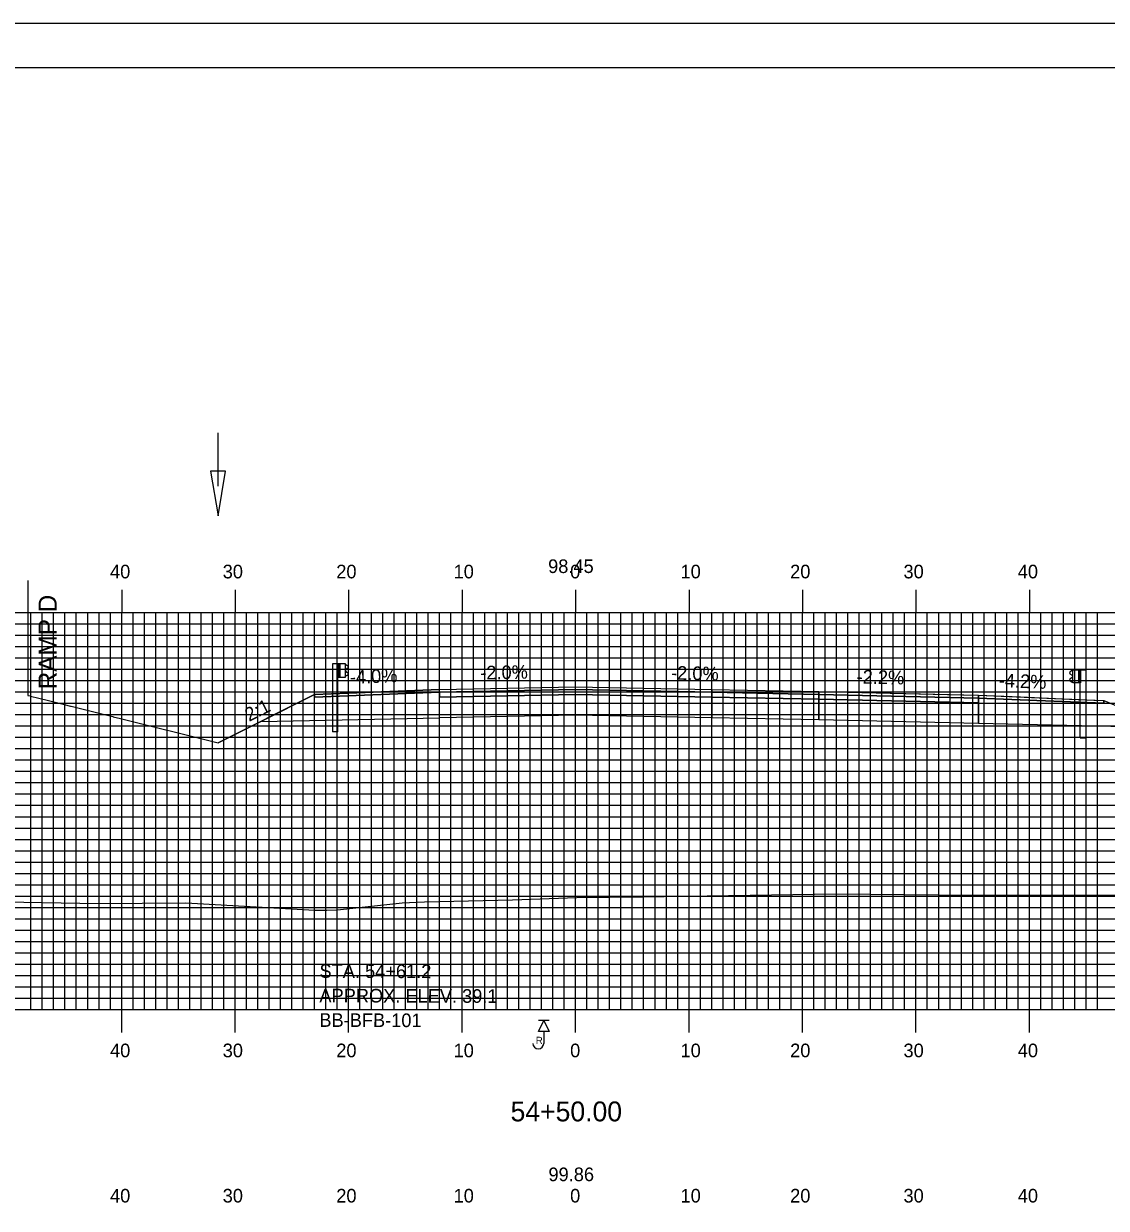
# Model space of a CAD drawing. Extents: x 1756282 to 1756625, y 442591 to 442811.
# Drawn here: x 1756398.9 to 1756494.3, y 442706.2 to 442810.5 of the extents above; entities that cross this region are included whole.
import ezdxf

# ---------------------------------------------------------------- set-up
doc = ezdxf.new("R2010")
doc.units = 0
for name, color, linetype in [('ANNOTATION', 7, 'Continuous'), ('BORDER', 7, 'Continuous'), ('BORING - REFUSAL', 7, 'Continuous'), ('D_Drainage_Ditch_Line', 7, 'Continuous'), ('D_Guardrail_Beam_Lt', 7, 'Continuous'), ('D_Guardrail_Beam_Rt', 7, 'Continuous'), ('D_Roadway_Centerline', 7, 'Continuous'), ('D_Roadway_Centerline_Text', 7, 'Continuous'), ('D_Roadway_Edge_Shoulder', 7, 'Continuous'), ('D_Roadway_Edge_TW', 7, 'Continuous'), ('D_Roadway_Pavement', 7, 'Continuous'), ('D_Roadway_SlopeLines', 7, 'Continuous'), ('D_Roadway_SubGrade', 7, 'Continuous'), ('H_V ANNOTATION', 7, 'Continuous'), ('MAJOR', 7, 'Continuous'), ('MINOR', 7, 'Continuous'), ('PLOT BOUNDARY', 7, 'Continuous'), ('S_Roadway_Centerline', 7, 'Continuous')]:
    doc.layers.add(name, color=color, linetype=linetype)

msp = doc.modelspace()

# ---------------------------------------------------------------- linework, layer by layer
at = {"layer": 'BORDER'}
msp.add_lwpolyline([(1756297.97, 442596.67), (1756617.97, 442596.67), (1756617.97, 442806.67), (1756297.97, 442806.67)], close=True, dxfattribs=at)
at = {"layer": 'BORING - REFUSAL'}
for p, q in [((1756445.25, 442722.71), (1756444.29, 442722.71)), ((1756444.77, 442721.75), (1756444.77, 442720.69))]:
    msp.add_line(p, q, dxfattribs=at)
msp.add_lwpolyline([(1756444.77, 442722.71), (1756445.25, 442721.75), (1756444.29, 442721.75)], close=True, dxfattribs=at)
msp.add_arc((1756444.28, 442720.69), 0.485, 180, 0, dxfattribs=at)
at = {"layer": 'D_Drainage_Ditch_Line'}
msp.add_line((1756416.06, 442769.8), (1756416.06, 442774.49), dxfattribs=at)
msp.add_lwpolyline([(1756416.72, 442771.11), (1756415.4, 442771.11), (1756416.06, 442767.17)], close=True, dxfattribs=at)
at = {"layer": 'D_Guardrail_Beam_Lt'}
for p, q in [((1756426.14, 442754.14), (1756426.14, 442748.14)), ((1756426.61, 442754.14), (1756426.14, 442754.14)), ((1756427.3, 442754.14), (1756426.61, 442754.14)), ((1756426.61, 442754.14), (1756426.61, 442752.97)), ((1756426.67, 442754.14), (1756426.67, 442752.97)), ((1756426.78, 442754.14), (1756426.78, 442752.97)), ((1756427.3, 442752.97), (1756427.3, 442754.14)), ((1756427.3, 442754.06), (1756427.37, 442754.04)), ((1756427.3, 442753.59), (1756427.3, 442753.52)), ((1756427.53, 442753.79), (1756427.34, 442753.66)), ((1756427.34, 442753.46), (1756427.53, 442753.32)), ((1756427.39, 442754.04), (1756427.53, 442753.94)), ((1756426.61, 442752.97), (1756427.3, 442752.97)), ((1756426.63, 442748.14), (1756426.63, 442752.97)), ((1756427.37, 442753.07), (1756427.3, 442753.06)), ((1756427.53, 442753.18), (1756427.39, 442753.08)), ((1756426.63, 442748.14), (1756426.14, 442748.14))]:
    msp.add_line(p, q, dxfattribs=at)
for centre, major_axis, start_param, end_param in [((1756427.38, 442753.59), (-0.0789, 0), 5.323254, 6.283185), ((1756427.38, 442753.52), (-0.0789, 0), 6.283185, 7.243116), ((1756427.37, 442754), (0.0417, 0), 0.959931, 1.376053), ((1756427.48, 442753.86), (0.0877, 0), 5.323254, 7.243116), ((1756427.48, 442753.25), (0.0877, 0), 5.323254, 7.243116), ((1756427.37, 442753.11), (0.0417, 0), 4.907132, 5.323254)]:
    msp.add_ellipse(centre, major_axis=major_axis, ratio=0.995501, start_param=start_param, end_param=end_param, dxfattribs=at)
at = {"layer": 'D_Guardrail_Beam_Rt'}
for p, q in [((1756491.29, 442753.51), (1756491.14, 442753.41)), ((1756491.38, 442753.53), (1756491.3, 442753.52)), ((1756491.38, 442753.62), (1756492.07, 442753.62)), ((1756491.38, 442752.45), (1756491.38, 442753.62)), ((1756491.9, 442753.62), (1756491.9, 442752.45)), ((1756492, 442753.62), (1756492, 442752.45)), ((1756492.07, 442753.62), (1756492.54, 442753.62)), ((1756492.07, 442753.62), (1756492.07, 442752.45)), ((1756492.54, 442753.62), (1756492.54, 442747.62)), ((1756491.14, 442753.27), (1756491.34, 442753.13)), ((1756491.34, 442752.94), (1756491.14, 442752.8)), ((1756491.14, 442752.66), (1756491.29, 442752.56)), ((1756491.3, 442752.55), (1756491.38, 442752.53)), ((1756491.37, 442753.07), (1756491.37, 442753)), ((1756492.07, 442752.45), (1756491.38, 442752.45)), ((1756492.04, 442747.62), (1756492.04, 442752.45)), ((1756492.04, 442747.62), (1756492.54, 442747.62))]:
    msp.add_line(p, q, dxfattribs=at)
for centre, major_axis, start_param, end_param in [((1756491.2, 442753.34), (-0.0877, 0), 5.323254, 7.243116), ((1756491.31, 442753.48), (-0.0417, 0), 4.907132, 5.323254), ((1756491.2, 442752.73), (-0.0877, 0), 5.323254, 7.243116), ((1756491.31, 442752.59), (-0.0417, 0), 0.959931, 1.376053), ((1756491.29, 442753.07), (0.0789, 0), 0, 0.959931), ((1756491.29, 442753), (0.0789, 0), 5.323254, 6.283185)]:
    msp.add_ellipse(centre, major_axis=major_axis, ratio=0.995501, start_param=start_param, end_param=end_param, dxfattribs=at)
at = {"layer": 'D_Roadway_Centerline'}
for points in [[(1756399.29, 442751.36), (1756399.5, 442751.31), (1756399.51, 442751.3), (1756399.54, 442751.29), (1756401.01, 442750.93), (1756402.4, 442750.58), (1756402.93, 442750.45), (1756403.05, 442750.42), (1756403.11, 442750.41), (1756403.82, 442750.23), (1756404.87, 442749.97), (1756405.69, 442749.76), (1756406.78, 442749.49), (1756406.81, 442749.48), (1756406.83, 442749.48), (1756407.19, 442749.39), (1756407.34, 442749.35), (1756416.06, 442747.18)], [(1756416.06, 442747.18), (1756419.82, 442749.06), (1756424.57, 442751.44), (1756427.57, 442751.56), (1756435.57, 442751.88), (1756447.57, 442752.12), (1756459.57, 442751.88), (1756469.02, 442751.69), (1756480.34, 442751.44), (1756480.5, 442751.43), (1756480.54, 442751.43), (1756481.68, 442751.41), (1756483.08, 442751.37), (1756486.77, 442751.22), (1756491.11, 442751.03), (1756491.3, 442751.03), (1756492.06, 442750.99), (1756492.64, 442750.97), (1756493.25, 442750.94), (1756494.12, 442750.91), (1756495.24, 442750.44)]]:
    msp.add_lwpolyline(points, dxfattribs=at)
at = {"layer": 'D_Roadway_Edge_Shoulder'}
for points in [[(1756435.57, 442751.88), (1756427.57, 442751.56), (1756427.57, 442751.56), (1756424.57, 442751.44), (1756424.57, 442751.19), (1756435.57, 442751.63)], [(1756483.08, 442751.37), (1756491.11, 442751.03), (1756491.11, 442751.03), (1756494.12, 442750.91), (1756494.12, 442750.66), (1756483.08, 442751.12)]]:
    msp.add_lwpolyline(points, close=True, dxfattribs=at)
at = {"layer": 'D_Roadway_Edge_TW'}
for points in [[(1756435.57, 442751.63), (1756435.57, 442751.88), (1756447.57, 442752.12), (1756459.57, 442751.88), (1756459.57, 442751.63), (1756447.57, 442751.87)], [(1756459.57, 442751.88), (1756469.02, 442751.69), (1756469.02, 442751.44), (1756459.57, 442751.63)], [(1756469.02, 442751.69), (1756483.08, 442751.37), (1756483.08, 442751.12), (1756469.02, 442751.44)]]:
    msp.add_lwpolyline(points, close=True, dxfattribs=at)
at = {"layer": 'D_Roadway_Pavement'}
for points in [[(1756435.57, 442751.21), (1756435.57, 442751.63), (1756447.57, 442751.87), (1756459.57, 442751.63), (1756459.57, 442751.21), (1756447.57, 442751.45)], [(1756459.57, 442751.63), (1756469.02, 442751.44), (1756469.02, 442751.02), (1756459.57, 442751.21)], [(1756469.02, 442751.44), (1756483.08, 442751.12), (1756483.08, 442750.71), (1756469.02, 442751.02)]]:
    msp.add_lwpolyline(points, close=True, dxfattribs=at)
for points in [[(1756435.57, 442751.63), (1756435.57, 442751.21)], [(1756483.08, 442751.12), (1756483.08, 442750.71)], [(1756483.08, 442751.12), (1756483.08, 442750.71)]]:
    msp.add_lwpolyline(points, dxfattribs=at)
at = {"layer": 'D_Roadway_SlopeLines'}
msp.add_lwpolyline([(1756424.57, 442751.44), (1756416.06, 442747.18)], dxfattribs=at)
at = {"layer": 'D_Roadway_SubGrade'}
msp.add_line((1756399.29, 442761.47), (1756399.29, 442751.36), dxfattribs=at)
for points in [[(1756435.57, 442751.21), (1756435.57, 442751.63), (1756424.57, 442751.19), (1756424.57, 442751.44), (1756419.82, 442749.06), (1756435.57, 442749.38)], [(1756435.57, 442749.38), (1756435.57, 442751.21), (1756447.57, 442751.45), (1756459.57, 442751.21), (1756459.57, 442749.38), (1756447.57, 442749.62)], [(1756459.57, 442751.21), (1756469.02, 442751.02), (1756469.02, 442749.19), (1756459.57, 442749.38)], [(1756469.02, 442751.02), (1756483.08, 442750.71), (1756483.08, 442748.87), (1756469.02, 442749.19)], [(1756483.08, 442750.71), (1756483.08, 442751.12), (1756494.12, 442750.66), (1756494.12, 442750.91), (1756499.94, 442748.5), (1756483.08, 442748.87)]]:
    msp.add_lwpolyline(points, close=True, dxfattribs=at)
at = {"layer": 'MAJOR'}
for p, q in [((1756407.57, 442760.67), (1756407.57, 442758.67)), ((1756417.57, 442760.67), (1756417.57, 442758.67)), ((1756427.57, 442760.67), (1756427.57, 442758.67)), ((1756437.57, 442760.67), (1756437.57, 442758.67)), ((1756447.57, 442760.67), (1756447.57, 442758.67)), ((1756457.57, 442760.67), (1756457.57, 442758.67)), ((1756467.57, 442760.67), (1756467.57, 442758.67)), ((1756477.57, 442760.67), (1756477.57, 442758.67)), ((1756487.57, 442760.67), (1756487.57, 442758.67)), ((1756307.57, 442758.67), (1756587.57, 442758.67)), ((1756307.57, 442758.67), (1756587.57, 442758.67)), ((1756407.57, 442723.67), (1756407.57, 442758.67)), ((1756417.57, 442723.67), (1756417.57, 442758.67)), ((1756427.57, 442723.67), (1756427.57, 442758.67)), ((1756437.57, 442723.67), (1756437.57, 442758.67)), ((1756447.57, 442723.67), (1756447.57, 442758.67)), ((1756457.57, 442723.67), (1756457.57, 442758.67)), ((1756467.57, 442723.67), (1756467.57, 442758.67)), ((1756477.57, 442723.67), (1756477.57, 442758.67)), ((1756487.57, 442723.67), (1756487.57, 442758.67)), ((1756307.57, 442753.67), (1756587.57, 442753.67)), ((1756307.57, 442748.67), (1756587.57, 442748.67)), ((1756307.57, 442743.67), (1756587.57, 442743.67)), ((1756307.57, 442738.67), (1756587.57, 442738.67)), ((1756307.57, 442733.67), (1756587.57, 442733.67)), ((1756307.57, 442728.67), (1756587.57, 442728.67)), ((1756307.57, 442723.67), (1756587.57, 442723.67)), ((1756307.57, 442723.67), (1756587.57, 442723.67)), ((1756407.57, 442721.66), (1756407.57, 442723.67)), ((1756417.57, 442721.66), (1756417.57, 442723.67)), ((1756427.57, 442721.66), (1756427.57, 442723.67)), ((1756437.57, 442721.66), (1756437.57, 442723.67)), ((1756447.57, 442721.66), (1756447.57, 442723.67)), ((1756457.57, 442721.66), (1756457.57, 442723.67)), ((1756467.57, 442721.66), (1756467.57, 442723.67)), ((1756477.57, 442721.66), (1756477.57, 442723.67)), ((1756487.57, 442721.66), (1756487.57, 442723.67))]:
    msp.add_line(p, q, dxfattribs=at)
at = {"layer": 'MINOR'}
for p, q in [((1756399.57, 442723.67), (1756399.57, 442758.67)), ((1756400.57, 442723.67), (1756400.57, 442758.67)), ((1756401.57, 442723.67), (1756401.57, 442758.67)), ((1756402.57, 442723.67), (1756402.57, 442758.67)), ((1756403.57, 442723.67), (1756403.57, 442758.67)), ((1756404.57, 442723.67), (1756404.57, 442758.67)), ((1756405.57, 442723.67), (1756405.57, 442758.67)), ((1756406.57, 442723.67), (1756406.57, 442758.67)), ((1756408.57, 442723.67), (1756408.57, 442758.67)), ((1756409.57, 442723.67), (1756409.57, 442758.67)), ((1756410.57, 442723.67), (1756410.57, 442758.67)), ((1756411.57, 442723.67), (1756411.57, 442758.67)), ((1756412.57, 442723.67), (1756412.57, 442758.67)), ((1756413.57, 442723.67), (1756413.57, 442758.67)), ((1756414.57, 442723.67), (1756414.57, 442758.67)), ((1756415.57, 442723.67), (1756415.57, 442758.67)), ((1756416.57, 442723.67), (1756416.57, 442758.67)), ((1756418.57, 442723.67), (1756418.57, 442758.67)), ((1756419.57, 442723.67), (1756419.57, 442758.67)), ((1756420.57, 442723.67), (1756420.57, 442758.67)), ((1756421.57, 442723.67), (1756421.57, 442758.67)), ((1756422.57, 442723.67), (1756422.57, 442758.67)), ((1756423.57, 442723.67), (1756423.57, 442758.67)), ((1756424.57, 442723.67), (1756424.57, 442758.67)), ((1756425.57, 442723.67), (1756425.57, 442758.67)), ((1756426.57, 442723.67), (1756426.57, 442758.67)), ((1756428.57, 442723.67), (1756428.57, 442758.67)), ((1756429.57, 442723.67), (1756429.57, 442758.67)), ((1756430.57, 442723.67), (1756430.57, 442758.67)), ((1756431.57, 442723.67), (1756431.57, 442758.67)), ((1756432.57, 442723.67), (1756432.57, 442758.67)), ((1756433.57, 442723.67), (1756433.57, 442758.67)), ((1756434.57, 442723.67), (1756434.57, 442758.67)), ((1756435.57, 442723.67), (1756435.57, 442758.67)), ((1756436.57, 442723.67), (1756436.57, 442758.67)), ((1756438.57, 442723.67), (1756438.57, 442758.67)), ((1756439.57, 442723.67), (1756439.57, 442758.67)), ((1756440.57, 442723.67), (1756440.57, 442758.67)), ((1756441.57, 442723.67), (1756441.57, 442758.67)), ((1756442.57, 442723.67), (1756442.57, 442758.67)), ((1756443.57, 442723.67), (1756443.57, 442758.67)), ((1756444.57, 442723.67), (1756444.57, 442758.67)), ((1756445.57, 442723.67), (1756445.57, 442758.67)), ((1756446.57, 442723.67), (1756446.57, 442758.67)), ((1756448.57, 442723.67), (1756448.57, 442758.67)), ((1756449.57, 442723.67), (1756449.57, 442758.67)), ((1756450.57, 442723.67), (1756450.57, 442758.67)), ((1756451.57, 442723.67), (1756451.57, 442758.67)), ((1756452.57, 442723.67), (1756452.57, 442758.67)), ((1756453.57, 442723.67), (1756453.57, 442758.67)), ((1756454.57, 442723.67), (1756454.57, 442758.67)), ((1756455.57, 442723.67), (1756455.57, 442758.67)), ((1756456.57, 442723.67), (1756456.57, 442758.67)), ((1756458.57, 442723.67), (1756458.57, 442758.67)), ((1756459.57, 442723.67), (1756459.57, 442758.67)), ((1756460.57, 442723.67), (1756460.57, 442758.67)), ((1756461.57, 442723.67), (1756461.57, 442758.67)), ((1756462.57, 442723.67), (1756462.57, 442758.67)), ((1756463.57, 442723.67), (1756463.57, 442758.67)), ((1756464.57, 442723.67), (1756464.57, 442758.67)), ((1756465.57, 442723.67), (1756465.57, 442758.67)), ((1756466.57, 442723.67), (1756466.57, 442758.67)), ((1756468.57, 442723.67), (1756468.57, 442758.67)), ((1756469.57, 442723.67), (1756469.57, 442758.67)), ((1756470.57, 442723.67), (1756470.57, 442758.67)), ((1756471.57, 442723.67), (1756471.57, 442758.67)), ((1756472.57, 442723.67), (1756472.57, 442758.67)), ((1756473.57, 442723.67), (1756473.57, 442758.67)), ((1756474.57, 442723.67), (1756474.57, 442758.67)), ((1756475.57, 442723.67), (1756475.57, 442758.67)), ((1756476.57, 442723.67), (1756476.57, 442758.67)), ((1756478.57, 442723.67), (1756478.57, 442758.67)), ((1756479.57, 442723.67), (1756479.57, 442758.67)), ((1756480.57, 442723.67), (1756480.57, 442758.67)), ((1756481.57, 442723.67), (1756481.57, 442758.67)), ((1756482.57, 442723.67), (1756482.57, 442758.67)), ((1756483.57, 442723.67), (1756483.57, 442758.67)), ((1756484.57, 442723.67), (1756484.57, 442758.67)), ((1756485.57, 442723.67), (1756485.57, 442758.67)), ((1756486.57, 442723.67), (1756486.57, 442758.67)), ((1756488.57, 442723.67), (1756488.57, 442758.67)), ((1756489.57, 442723.67), (1756489.57, 442758.67)), ((1756490.57, 442723.67), (1756490.57, 442758.67)), ((1756491.57, 442723.67), (1756491.57, 442758.67)), ((1756492.57, 442723.67), (1756492.57, 442758.67)), ((1756493.57, 442723.67), (1756493.57, 442758.67)), ((1756307.57, 442757.67), (1756587.57, 442757.67)), ((1756307.57, 442756.67), (1756587.57, 442756.67)), ((1756307.57, 442755.67), (1756587.57, 442755.67)), ((1756307.57, 442754.67), (1756587.57, 442754.67)), ((1756307.57, 442752.67), (1756587.57, 442752.67)), ((1756307.57, 442751.67), (1756587.57, 442751.67)), ((1756307.57, 442750.67), (1756587.57, 442750.67)), ((1756307.57, 442749.67), (1756587.57, 442749.67)), ((1756307.57, 442747.67), (1756587.57, 442747.67)), ((1756307.57, 442746.67), (1756587.57, 442746.67)), ((1756307.57, 442745.67), (1756587.57, 442745.67)), ((1756307.57, 442744.67), (1756587.57, 442744.67)), ((1756307.57, 442742.67), (1756587.57, 442742.67)), ((1756307.57, 442741.67), (1756587.57, 442741.67)), ((1756307.57, 442740.67), (1756587.57, 442740.67)), ((1756307.57, 442739.67), (1756587.57, 442739.67)), ((1756307.57, 442737.67), (1756587.57, 442737.67)), ((1756307.57, 442736.67), (1756587.57, 442736.67)), ((1756307.57, 442735.67), (1756587.57, 442735.67)), ((1756307.57, 442734.67), (1756587.57, 442734.67)), ((1756307.57, 442732.67), (1756587.57, 442732.67)), ((1756307.57, 442731.67), (1756587.57, 442731.67)), ((1756307.57, 442730.67), (1756587.57, 442730.67)), ((1756307.57, 442729.67), (1756587.57, 442729.67)), ((1756307.57, 442727.67), (1756587.57, 442727.67)), ((1756307.57, 442726.67), (1756587.57, 442726.67)), ((1756307.57, 442725.67), (1756587.57, 442725.67)), ((1756307.57, 442724.67), (1756587.57, 442724.67))]:
    msp.add_line(p, q, dxfattribs=at)
at = {"layer": 'PLOT BOUNDARY'}
msp.add_lwpolyline([(1756281.78, 442590.55), (1756621.78, 442590.55), (1756621.78, 442810.55), (1756281.78, 442810.55)], close=True, dxfattribs=at)
at = {"layer": 'S_Roadway_Centerline'}
msp.add_lwpolyline([(1756392.32, 442733.26), (1756405.53, 442733.01), (1756413.22, 442733.07), (1756424.6, 442732.44), (1756425.66, 442732.44), (1756426.59, 442732.45), (1756432.29, 442733.09), (1756434.26, 442733.16), (1756442.01, 442733.34), (1756447.68, 442733.55), (1756453.5, 442733.61), (1756470.52, 442733.86), (1756482.57, 442733.74), (1756495.91, 442733.76), (1756504.14, 442733.66), (1756527.63, 442734.03), (1756527.67, 442734.03), (1756527.69, 442734.03), (1756527.75, 442734.03), (1756548.47, 442734.25)], dxfattribs=at)

# ---------------------------------------------------------------- texts
at = {"layer": 'ANNOTATION'}
for s, height, rotation, p in [('RAMP D', 1.6, 90, (1756401.84, 442751.9)), ('-4.0%', 1.2, 2.2906, (1756427.7, 442752.36)), ('-2.0%', 1.2, 1.1458, (1756439.18, 442752.75)), ('-2.0%', 1.2, 358.8542, (1756455.98, 442752.75)), ('-2.2%', 1.2, 358.7197, (1756472.33, 442752.41)), ('-4.2%', 1.2, 357.5798, (1756484.85, 442752.1)), ('2:1', 1.2, 26.5651, (1756418.8, 442749.02))]:
    msp.add_text(s, height=height, rotation=rotation, dxfattribs=at).set_placement(p)
at = {"layer": 'BORING - REFUSAL'}
for s, p in [('STA. 54+61.2', (1756425, 442726.47)), ('APPROX. ELEV. 39.1', (1756424.99, 442724.31)), ('BB-BFB-101', (1756424.99, 442722.15))]:
    msp.add_text(s, height=1.2, rotation=359.8142, dxfattribs=at).set_placement(p)
msp.add_text('R', height=0.64, dxfattribs=at).set_placement((1756444.06, 442720.63))
at = {"layer": 'D_Roadway_Centerline'}
for s, p in [('C', (1756447.56, 442752.12)), ('L', (1756447.57, 442752.11))]:
    msp.add_text(s, height=0.0146, dxfattribs=at).set_placement(p)
at = {"layer": 'D_Roadway_Centerline_Text'}
for s, p in [('98.45', (1756445.15, 442762.14)), ('99.86', (1756445.18, 442708.55))]:
    msp.add_text(s, height=1.2, dxfattribs=at).set_placement(p)
at = {"layer": 'H_V ANNOTATION'}
for s, height, p in [('40', 1.2, (1756406.54, 442761.67)), ('30', 1.2, (1756416.47, 442761.67)), ('20', 1.2, (1756426.48, 442761.67)), ('10', 1.2, (1756436.82, 442761.67)), ('0', 1.2, (1756447.09, 442761.67)), ('10', 1.2, (1756456.82, 442761.67)), ('20', 1.2, (1756466.48, 442761.67)), ('30', 1.2, (1756476.47, 442761.67)), ('40', 1.2, (1756486.54, 442761.67)), ('40', 1.2, (1756406.54, 442719.47)), ('30', 1.2, (1756416.47, 442719.47)), ('20', 1.2, (1756426.48, 442719.47)), ('10', 1.2, (1756436.82, 442719.47)), ('0', 1.2, (1756447.09, 442719.47)), ('10', 1.2, (1756456.82, 442719.47)), ('20', 1.2, (1756466.48, 442719.47)), ('30', 1.2, (1756476.47, 442719.47)), ('40', 1.2, (1756486.54, 442719.47)), ('54+50.00', 1.75, (1756441.84, 442713.82)), ('40', 1.2, (1756406.54, 442706.67)), ('30', 1.2, (1756416.47, 442706.67)), ('20', 1.2, (1756426.48, 442706.67)), ('10', 1.2, (1756436.82, 442706.67)), ('0', 1.2, (1756447.09, 442706.67)), ('10', 1.2, (1756456.82, 442706.67)), ('20', 1.2, (1756466.48, 442706.67)), ('30', 1.2, (1756476.47, 442706.67)), ('40', 1.2, (1756486.54, 442706.67))]:
    msp.add_text(s, height=height, dxfattribs=at).set_placement(p)

doc.saveas('drawing.dxf')
